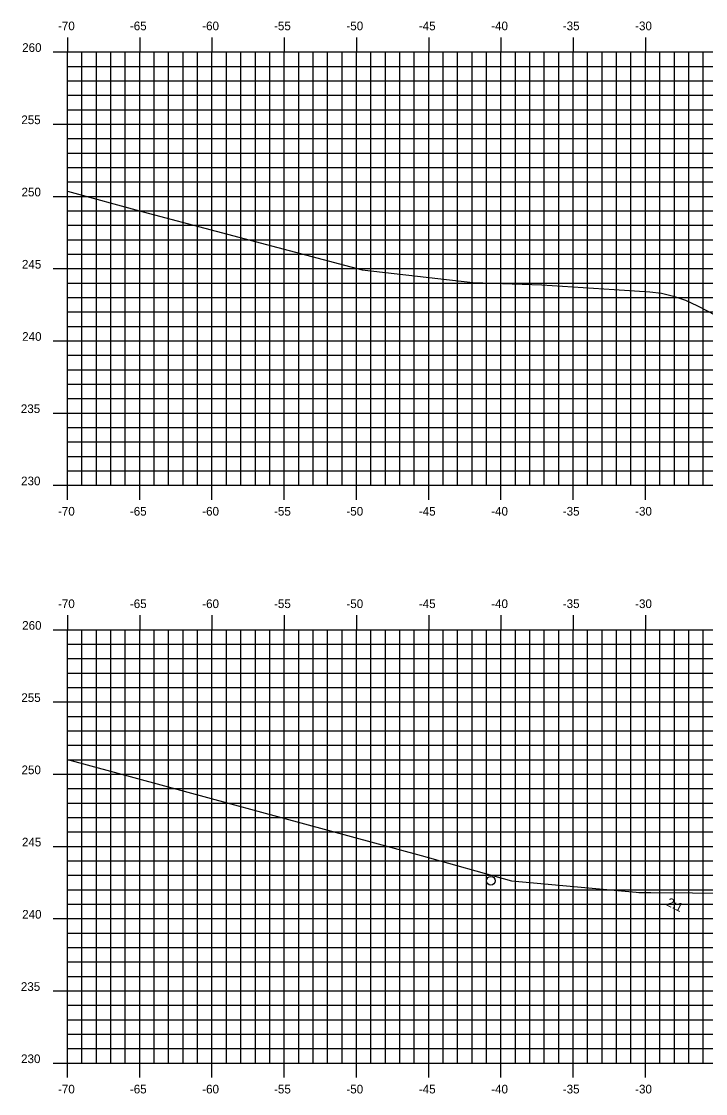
# Model space of a CAD drawing. Extents: x 1170543 to 1177585, y 609599 to 610623.
# Drawn here: x 1173436.1 to 1173483.5, y 610275.7 to 610349.9 of the extents above; entities that cross this region are included whole.
import ezdxf

# ---------------------------------------------------------------- set-up
doc = ezdxf.new("R2010")
doc.units = 0
for name, color, linetype in [('ANNOTATION', 7, 'Continuous'), ('H_V ANNOTATION', 7, 'Continuous'), ('MAJOR', 7, 'Continuous'), ('MINOR', 7, 'Continuous'), ('S_Drainage_Invert', 7, 'Continuous'), ('S_Roadway_Centerline', 7, 'Continuous')]:
    doc.layers.add(name, color=color, linetype=linetype)

msp = doc.modelspace()

# ---------------------------------------------------------------- linework, layer by layer
at = {"layer": 'MAJOR'}
for p, q in [((1173439.306, 610348.803), (1173439.306, 610347.801)), ((1173444.306, 610348.803), (1173444.306, 610347.801)), ((1173449.306, 610348.803), (1173449.306, 610347.801)), ((1173454.306, 610348.803), (1173454.306, 610347.801)), ((1173459.306, 610348.803), (1173459.306, 610347.801)), ((1173464.306, 610348.803), (1173464.306, 610347.801)), ((1173469.306, 610348.803), (1173469.306, 610347.801)), ((1173474.306, 610348.803), (1173474.306, 610347.801)), ((1173479.306, 610348.803), (1173479.306, 610347.801)), ((1173438.304, 610347.801), (1173439.306, 610347.801)), ((1173439.306, 610347.801), (1173579.306, 610347.801)), ((1173439.306, 610317.801), (1173439.306, 610347.801)), ((1173439.306, 610317.801), (1173439.306, 610347.801)), ((1173439.306, 610347.801), (1173579.306, 610347.801)), ((1173444.306, 610317.801), (1173444.306, 610347.801)), ((1173449.306, 610317.801), (1173449.306, 610347.801)), ((1173454.306, 610317.801), (1173454.306, 610347.801)), ((1173459.306, 610317.801), (1173459.306, 610347.801)), ((1173464.306, 610317.801), (1173464.306, 610347.801)), ((1173469.306, 610317.801), (1173469.306, 610347.801)), ((1173474.306, 610317.801), (1173474.306, 610347.801)), ((1173479.306, 610317.801), (1173479.306, 610347.801)), ((1173438.304, 610342.801), (1173439.306, 610342.801)), ((1173439.306, 610342.801), (1173579.306, 610342.801)), ((1173438.304, 610337.801), (1173439.306, 610337.801)), ((1173439.306, 610337.801), (1173579.306, 610337.801)), ((1173438.304, 610332.801), (1173439.306, 610332.801)), ((1173439.306, 610332.801), (1173579.306, 610332.801)), ((1173438.304, 610327.801), (1173439.306, 610327.801)), ((1173439.306, 610327.801), (1173579.306, 610327.801)), ((1173438.304, 610322.801), (1173439.306, 610322.801)), ((1173439.306, 610322.801), (1173579.306, 610322.801)), ((1173438.304, 610317.801), (1173439.306, 610317.801)), ((1173439.306, 610317.801), (1173579.306, 610317.801)), ((1173439.306, 610317.801), (1173579.306, 610317.801)), ((1173439.306, 610316.799), (1173439.306, 610317.801)), ((1173444.306, 610316.799), (1173444.306, 610317.801)), ((1173449.306, 610316.799), (1173449.306, 610317.801)), ((1173454.306, 610316.799), (1173454.306, 610317.801)), ((1173459.306, 610316.799), (1173459.306, 610317.801)), ((1173464.306, 610316.799), (1173464.306, 610317.801)), ((1173469.306, 610316.799), (1173469.306, 610317.801)), ((1173474.306, 610316.799), (1173474.306, 610317.801)), ((1173479.306, 610316.799), (1173479.306, 610317.801)), ((1173439.306, 610308.803), (1173439.306, 610307.801)), ((1173444.306, 610308.803), (1173444.306, 610307.801)), ((1173449.306, 610308.803), (1173449.306, 610307.801)), ((1173454.306, 610308.803), (1173454.306, 610307.801)), ((1173459.306, 610308.803), (1173459.306, 610307.801)), ((1173464.306, 610308.803), (1173464.306, 610307.801)), ((1173469.306, 610308.803), (1173469.306, 610307.801)), ((1173474.306, 610308.803), (1173474.306, 610307.801)), ((1173479.306, 610308.803), (1173479.306, 610307.801)), ((1173438.304, 610307.801), (1173439.306, 610307.801)), ((1173439.306, 610307.801), (1173579.306, 610307.801)), ((1173439.306, 610277.801), (1173439.306, 610307.801)), ((1173439.306, 610277.801), (1173439.306, 610307.801)), ((1173439.306, 610307.801), (1173579.306, 610307.801)), ((1173444.306, 610277.801), (1173444.306, 610307.801)), ((1173449.306, 610277.801), (1173449.306, 610307.801)), ((1173454.306, 610277.801), (1173454.306, 610307.801)), ((1173459.306, 610277.801), (1173459.306, 610307.801)), ((1173464.306, 610277.801), (1173464.306, 610307.801)), ((1173469.306, 610277.801), (1173469.306, 610307.801)), ((1173474.306, 610277.801), (1173474.306, 610307.801)), ((1173479.306, 610277.801), (1173479.306, 610307.801)), ((1173438.304, 610302.801), (1173439.306, 610302.801)), ((1173439.306, 610302.801), (1173579.306, 610302.801)), ((1173438.304, 610297.801), (1173439.306, 610297.801)), ((1173439.306, 610297.801), (1173579.306, 610297.801)), ((1173438.304, 610292.801), (1173439.306, 610292.801)), ((1173439.306, 610292.801), (1173579.306, 610292.801)), ((1173438.304, 610287.801), (1173439.306, 610287.801)), ((1173439.306, 610287.801), (1173579.306, 610287.801)), ((1173438.304, 610282.801), (1173439.306, 610282.801)), ((1173439.306, 610282.801), (1173579.306, 610282.801)), ((1173438.304, 610277.801), (1173439.306, 610277.801)), ((1173439.306, 610277.801), (1173579.306, 610277.801)), ((1173439.306, 610277.801), (1173579.306, 610277.801)), ((1173439.306, 610276.799), (1173439.306, 610277.801)), ((1173444.306, 610276.799), (1173444.306, 610277.801)), ((1173449.306, 610276.799), (1173449.306, 610277.801)), ((1173454.306, 610276.799), (1173454.306, 610277.801)), ((1173459.306, 610276.799), (1173459.306, 610277.801)), ((1173464.306, 610276.799), (1173464.306, 610277.801)), ((1173469.306, 610276.799), (1173469.306, 610277.801)), ((1173474.306, 610276.799), (1173474.306, 610277.801)), ((1173479.306, 610276.799), (1173479.306, 610277.801))]:
    msp.add_line(p, q, dxfattribs=at)
at = {"layer": 'MINOR'}
for p, q in [((1173440.306, 610317.801), (1173440.306, 610347.801)), ((1173441.306, 610317.801), (1173441.306, 610347.801)), ((1173442.306, 610317.801), (1173442.306, 610347.801)), ((1173443.306, 610317.801), (1173443.306, 610347.801)), ((1173445.306, 610317.801), (1173445.306, 610347.801)), ((1173446.306, 610317.801), (1173446.306, 610347.801)), ((1173447.306, 610317.801), (1173447.306, 610347.801)), ((1173448.306, 610317.801), (1173448.306, 610347.801)), ((1173450.306, 610317.801), (1173450.306, 610347.801)), ((1173451.306, 610317.801), (1173451.306, 610347.801)), ((1173452.306, 610317.801), (1173452.306, 610347.801)), ((1173453.306, 610317.801), (1173453.306, 610347.801)), ((1173455.306, 610317.801), (1173455.306, 610347.801)), ((1173456.306, 610317.801), (1173456.306, 610347.801)), ((1173457.306, 610317.801), (1173457.306, 610347.801)), ((1173458.306, 610317.801), (1173458.306, 610347.801)), ((1173460.306, 610317.801), (1173460.306, 610347.801)), ((1173461.306, 610317.801), (1173461.306, 610347.801)), ((1173462.306, 610317.801), (1173462.306, 610347.801)), ((1173463.306, 610317.801), (1173463.306, 610347.801)), ((1173465.306, 610317.801), (1173465.306, 610347.801)), ((1173466.306, 610317.801), (1173466.306, 610347.801)), ((1173467.306, 610317.801), (1173467.306, 610347.801)), ((1173468.306, 610317.801), (1173468.306, 610347.801)), ((1173470.306, 610317.801), (1173470.306, 610347.801)), ((1173471.306, 610317.801), (1173471.306, 610347.801)), ((1173472.306, 610317.801), (1173472.306, 610347.801)), ((1173473.306, 610317.801), (1173473.306, 610347.801)), ((1173475.306, 610317.801), (1173475.306, 610347.801)), ((1173476.306, 610317.801), (1173476.306, 610347.801)), ((1173477.306, 610317.801), (1173477.306, 610347.801)), ((1173478.306, 610317.801), (1173478.306, 610347.801)), ((1173480.306, 610317.801), (1173480.306, 610347.801)), ((1173481.306, 610317.801), (1173481.306, 610347.801)), ((1173482.306, 610317.801), (1173482.306, 610347.801)), ((1173483.306, 610317.801), (1173483.306, 610347.801)), ((1173439.306, 610346.801), (1173579.306, 610346.801)), ((1173439.306, 610346.801), (1173440.308, 610346.801)), ((1173439.306, 610345.801), (1173579.306, 610345.801)), ((1173439.306, 610345.801), (1173440.308, 610345.801)), ((1173439.306, 610344.801), (1173579.306, 610344.801)), ((1173439.306, 610344.801), (1173440.308, 610344.801)), ((1173439.306, 610343.801), (1173579.306, 610343.801)), ((1173439.306, 610343.801), (1173440.308, 610343.801)), ((1173439.306, 610341.801), (1173579.306, 610341.801)), ((1173439.306, 610341.801), (1173440.308, 610341.801)), ((1173439.306, 610340.801), (1173579.306, 610340.801)), ((1173439.306, 610340.801), (1173440.308, 610340.801)), ((1173439.306, 610339.801), (1173579.306, 610339.801)), ((1173439.306, 610339.801), (1173440.308, 610339.801)), ((1173439.306, 610338.801), (1173579.306, 610338.801)), ((1173439.306, 610338.801), (1173440.308, 610338.801)), ((1173439.306, 610336.801), (1173579.306, 610336.801)), ((1173439.306, 610336.801), (1173440.308, 610336.801)), ((1173439.306, 610335.801), (1173579.306, 610335.801)), ((1173439.306, 610335.801), (1173440.308, 610335.801)), ((1173439.306, 610334.801), (1173579.306, 610334.801)), ((1173439.306, 610334.801), (1173440.308, 610334.801)), ((1173439.306, 610333.801), (1173579.306, 610333.801)), ((1173439.306, 610333.801), (1173440.308, 610333.801)), ((1173439.306, 610331.801), (1173579.306, 610331.801)), ((1173439.306, 610331.801), (1173440.308, 610331.801)), ((1173439.306, 610330.801), (1173579.306, 610330.801)), ((1173439.306, 610330.801), (1173440.308, 610330.801)), ((1173439.306, 610329.801), (1173579.306, 610329.801)), ((1173439.306, 610329.801), (1173440.308, 610329.801)), ((1173439.306, 610328.801), (1173579.306, 610328.801)), ((1173439.306, 610328.801), (1173440.308, 610328.801)), ((1173439.306, 610326.801), (1173579.306, 610326.801)), ((1173439.306, 610326.801), (1173440.308, 610326.801)), ((1173439.306, 610325.801), (1173579.306, 610325.801)), ((1173439.306, 610325.801), (1173440.308, 610325.801)), ((1173439.306, 610324.801), (1173579.306, 610324.801)), ((1173439.306, 610324.801), (1173440.308, 610324.801)), ((1173439.306, 610323.801), (1173579.306, 610323.801)), ((1173439.306, 610323.801), (1173440.308, 610323.801)), ((1173439.306, 610321.801), (1173579.306, 610321.801)), ((1173439.306, 610321.801), (1173440.308, 610321.801)), ((1173439.306, 610320.801), (1173579.306, 610320.801)), ((1173439.306, 610320.801), (1173440.308, 610320.801)), ((1173439.306, 610319.801), (1173579.306, 610319.801)), ((1173439.306, 610319.801), (1173440.308, 610319.801)), ((1173439.306, 610318.801), (1173579.306, 610318.801)), ((1173439.306, 610318.801), (1173440.308, 610318.801)), ((1173440.306, 610277.801), (1173440.306, 610307.801)), ((1173441.306, 610277.801), (1173441.306, 610307.801)), ((1173442.306, 610277.801), (1173442.306, 610307.801)), ((1173443.306, 610277.801), (1173443.306, 610307.801)), ((1173445.306, 610277.801), (1173445.306, 610307.801)), ((1173446.306, 610277.801), (1173446.306, 610307.801)), ((1173447.306, 610277.801), (1173447.306, 610307.801)), ((1173448.306, 610277.801), (1173448.306, 610307.801)), ((1173450.306, 610277.801), (1173450.306, 610307.801)), ((1173451.306, 610277.801), (1173451.306, 610307.801)), ((1173452.306, 610277.801), (1173452.306, 610307.801)), ((1173453.306, 610277.801), (1173453.306, 610307.801)), ((1173455.306, 610277.801), (1173455.306, 610307.801)), ((1173456.306, 610277.801), (1173456.306, 610307.801)), ((1173457.306, 610277.801), (1173457.306, 610307.801)), ((1173458.306, 610277.801), (1173458.306, 610307.801)), ((1173460.306, 610277.801), (1173460.306, 610307.801)), ((1173461.306, 610277.801), (1173461.306, 610307.801)), ((1173462.306, 610277.801), (1173462.306, 610307.801)), ((1173463.306, 610277.801), (1173463.306, 610307.801)), ((1173465.306, 610277.801), (1173465.306, 610307.801)), ((1173466.306, 610277.801), (1173466.306, 610307.801)), ((1173467.306, 610277.801), (1173467.306, 610307.801)), ((1173468.306, 610277.801), (1173468.306, 610307.801)), ((1173470.306, 610277.801), (1173470.306, 610307.801)), ((1173471.306, 610277.801), (1173471.306, 610307.801)), ((1173472.306, 610277.801), (1173472.306, 610307.801)), ((1173473.306, 610277.801), (1173473.306, 610307.801)), ((1173475.306, 610277.801), (1173475.306, 610307.801)), ((1173476.306, 610277.801), (1173476.306, 610307.801)), ((1173477.306, 610277.801), (1173477.306, 610307.801)), ((1173478.306, 610277.801), (1173478.306, 610307.801)), ((1173480.306, 610277.801), (1173480.306, 610307.801)), ((1173481.306, 610277.801), (1173481.306, 610307.801)), ((1173482.306, 610277.801), (1173482.306, 610307.801)), ((1173483.306, 610277.801), (1173483.306, 610307.801)), ((1173439.306, 610306.801), (1173579.306, 610306.801)), ((1173439.306, 610306.801), (1173440.308, 610306.801)), ((1173439.306, 610305.801), (1173579.306, 610305.801)), ((1173439.306, 610305.801), (1173440.308, 610305.801)), ((1173439.306, 610304.801), (1173579.306, 610304.801)), ((1173439.306, 610304.801), (1173440.308, 610304.801)), ((1173439.306, 610303.801), (1173579.306, 610303.801)), ((1173439.306, 610303.801), (1173440.308, 610303.801)), ((1173439.306, 610301.801), (1173579.306, 610301.801)), ((1173439.306, 610301.801), (1173440.308, 610301.801)), ((1173439.306, 610300.801), (1173579.306, 610300.801)), ((1173439.306, 610300.801), (1173440.308, 610300.801)), ((1173439.306, 610299.801), (1173579.306, 610299.801)), ((1173439.306, 610299.801), (1173440.308, 610299.801)), ((1173439.306, 610298.801), (1173579.306, 610298.801)), ((1173439.306, 610298.801), (1173440.308, 610298.801)), ((1173439.306, 610296.801), (1173579.306, 610296.801)), ((1173439.306, 610296.801), (1173440.308, 610296.801)), ((1173439.306, 610295.801), (1173579.306, 610295.801)), ((1173439.306, 610295.801), (1173440.308, 610295.801)), ((1173439.306, 610294.801), (1173579.306, 610294.801)), ((1173439.306, 610294.801), (1173440.308, 610294.801)), ((1173439.306, 610293.801), (1173579.306, 610293.801)), ((1173439.306, 610293.801), (1173440.308, 610293.801)), ((1173439.306, 610291.801), (1173579.306, 610291.801)), ((1173439.306, 610291.801), (1173440.308, 610291.801)), ((1173439.306, 610290.801), (1173579.306, 610290.801)), ((1173439.306, 610290.801), (1173440.308, 610290.801)), ((1173439.306, 610289.801), (1173579.306, 610289.801)), ((1173439.306, 610289.801), (1173440.308, 610289.801)), ((1173439.306, 610288.801), (1173579.306, 610288.801)), ((1173439.306, 610288.801), (1173440.308, 610288.801)), ((1173439.306, 610286.801), (1173579.306, 610286.801)), ((1173439.306, 610286.801), (1173440.308, 610286.801)), ((1173439.306, 610285.801), (1173579.306, 610285.801)), ((1173439.306, 610285.801), (1173440.308, 610285.801)), ((1173439.306, 610284.801), (1173579.306, 610284.801)), ((1173439.306, 610284.801), (1173440.308, 610284.801)), ((1173439.306, 610283.801), (1173579.306, 610283.801)), ((1173439.306, 610283.801), (1173440.308, 610283.801)), ((1173439.306, 610281.801), (1173579.306, 610281.801)), ((1173439.306, 610281.801), (1173440.308, 610281.801)), ((1173439.306, 610280.801), (1173579.306, 610280.801)), ((1173439.306, 610280.801), (1173440.308, 610280.801)), ((1173439.306, 610279.801), (1173579.306, 610279.801)), ((1173439.306, 610279.801), (1173440.308, 610279.801)), ((1173439.306, 610278.801), (1173579.306, 610278.801)), ((1173439.306, 610278.801), (1173440.308, 610278.801))]:
    msp.add_line(p, q, dxfattribs=at)
at = {"layer": 'S_Drainage_Invert'}
msp.add_circle((1173468.608, 610290.428), 0.3, dxfattribs=at)
at = {"layer": 'S_Roadway_Centerline'}
for points in [[(1173439.306, 610338.172), (1173444.538, 610336.736), (1173459.707, 610332.714), (1173467.368, 610331.848), (1173472.14, 610331.673), (1173477.135, 610331.35), (1173479.612, 610331.189), (1173480.429, 610331.093), (1173481.253, 610330.901), (1173482.084, 610330.612), (1173482.92, 610330.225), (1173491.242, 610325.897)], [(1173439.306, 610298.826), (1173463.777, 610292.177), (1173470.03, 610290.408), (1173478.666, 610289.628), (1173478.85, 610289.608), (1173479.691, 610289.602), (1173494.103, 610289.497)]]:
    msp.add_lwpolyline(points, dxfattribs=at)

# ---------------------------------------------------------------- texts
at = {"layer": 'ANNOTATION'}
msp.add_text('2:1', height=0.6, rotation=333.43495, dxfattribs=at).set_placement((1173480.709, 610288.744))
at = {"layer": 'H_V ANNOTATION'}
for s, p in [('-70', (1173438.648, 610349.301)), ('-65', (1173443.624, 610349.301)), ('-60', (1173448.632, 610349.301)), ('-55', (1173453.602, 610349.301)), ('-50', (1173458.61, 610349.301)), ('-45', (1173463.624, 610349.301)), ('-40', (1173468.632, 610349.301)), ('-35', (1173473.586, 610349.301)), ('-30', (1173478.594, 610349.301)), ('260', (1173436.168, 610347.801)), ('255', (1173436.109, 610342.801)), ('250', (1173436.125, 610337.801)), ('245', (1173436.152, 610332.801)), ('240', (1173436.168, 610327.801)), ('235', (1173436.077, 610322.801)), ('230', (1173436.093, 610317.801)), ('-70', (1173438.648, 610315.701)), ('-65', (1173443.624, 610315.701)), ('-60', (1173448.632, 610315.701)), ('-55', (1173453.602, 610315.701)), ('-50', (1173458.61, 610315.701)), ('-45', (1173463.624, 610315.701)), ('-40', (1173468.632, 610315.701)), ('-35', (1173473.586, 610315.701)), ('-30', (1173478.594, 610315.701)), ('-70', (1173438.648, 610309.301)), ('-65', (1173443.624, 610309.301)), ('-60', (1173448.632, 610309.301)), ('-55', (1173453.602, 610309.301)), ('-50', (1173458.61, 610309.301)), ('-45', (1173463.624, 610309.301)), ('-40', (1173468.632, 610309.301)), ('-35', (1173473.586, 610309.301)), ('-30', (1173478.594, 610309.301)), ('260', (1173436.168, 610307.801)), ('255', (1173436.109, 610302.801)), ('250', (1173436.125, 610297.801)), ('245', (1173436.152, 610292.801)), ('240', (1173436.168, 610287.801)), ('235', (1173436.077, 610282.801)), ('230', (1173436.093, 610277.801)), ('-70', (1173438.648, 610275.701)), ('-65', (1173443.624, 610275.701)), ('-60', (1173448.632, 610275.701)), ('-55', (1173453.602, 610275.701)), ('-50', (1173458.61, 610275.701)), ('-45', (1173463.624, 610275.701)), ('-40', (1173468.632, 610275.701)), ('-35', (1173473.586, 610275.701)), ('-30', (1173478.594, 610275.701))]:
    msp.add_text(s, height=0.6, dxfattribs=at).set_placement(p)

doc.saveas('drawing.dxf')
